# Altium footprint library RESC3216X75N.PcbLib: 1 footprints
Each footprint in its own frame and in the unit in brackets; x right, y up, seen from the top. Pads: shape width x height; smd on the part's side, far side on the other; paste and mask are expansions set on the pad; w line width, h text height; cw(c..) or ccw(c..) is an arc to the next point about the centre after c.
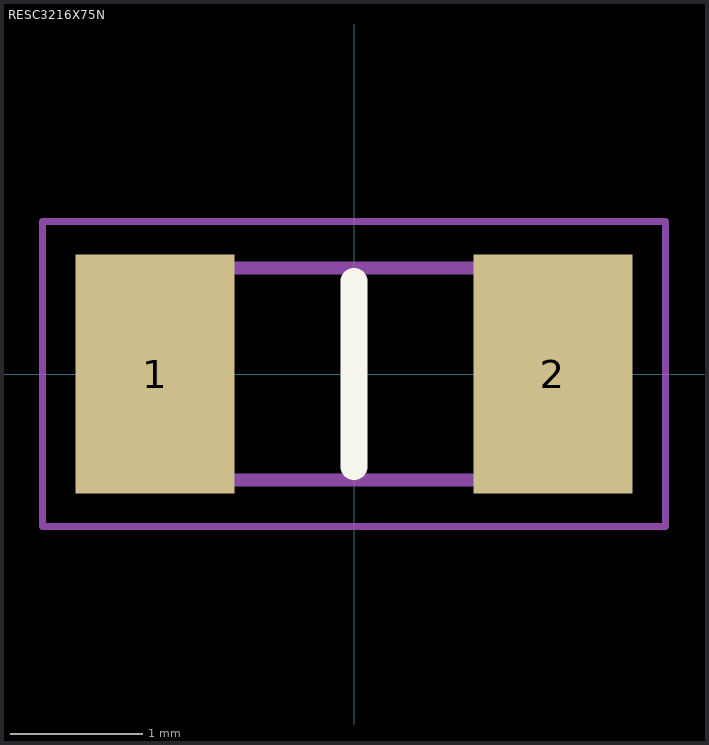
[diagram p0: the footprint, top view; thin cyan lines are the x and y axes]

## RESC3216X75N [mm]
pads (2):
  rect 1.2x1.8 smd: 1(-1.5,0) 2(1.5,0)
Top Overlay:
  lines w0.2: 0,-0.7 0,0.7
Mechanical 15:
  lines w0.1: -1.6,-0.8 1.6,-0.8 1.6,0.8 -1.6,0.8 -1.6,-0.8
Mechanical 20:
  lines w0.05: -2.35,-1.15 2.35,-1.15 2.35,1.15 -2.35,1.15 -2.35,-1.15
